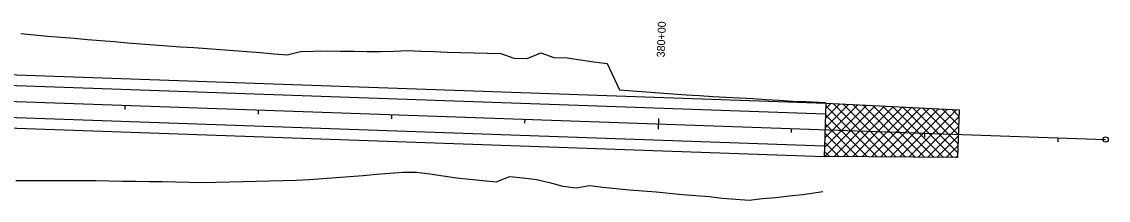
# Model space of a CAD drawing. Extents: x 881426 to 887360, y 1564404 to 1567430.
# Drawn here: x 886545 to 887360, y 1564404 to 1564538 of the extents above; entities that cross this region are included whole.
import ezdxf

# ---------------------------------------------------------------- set-up
doc = ezdxf.new("R2010")
doc.units = 0
for name, color, linetype in [('R_Axis', 7, 'Continuous'), ('R_Horz Alg', 7, 'Continuous'), ('R_Horz Alg Annot', 7, 'Continuous'), ('R_Proposed Const Limits_Cut', 7, 'Continuous'), ('R_Proposed Const Limits_Fill', 7, 'Continuous'), ('R_Proposed Road_Lane', 7, 'Continuous'), ('R_Proposed Road_Shoulder', 7, 'Continuous')]:
    doc.layers.add(name, color=color, linetype=linetype)

msp = doc.modelspace()

# ---------------------------------------------------------------- linework, layer by layer
at = {"layer": 'R_Axis'}
for p, q in [((887146.85, 1564444.07), (887178.58, 1564475.8)), ((887147.1, 1564451.4), (887171.84, 1564476.14)), ((887147.21, 1564437.36), (887185.31, 1564475.46)), ((887147.36, 1564458.72), (887165.11, 1564476.48)), ((887147.61, 1564466.05), (887158.38, 1564476.81)), ((887147.87, 1564473.37), (887151.65, 1564477.15)), ((887147.94, 1564475.39), (887186.33, 1564437)), ((887153.33, 1564477.07), (887193.47, 1564436.93)), ((887154.21, 1564437.29), (887192.04, 1564475.12)), ((887160.78, 1564476.69), (887200.61, 1564436.86)), ((887161.22, 1564437.23), (887198.77, 1564474.78)), ((887168.22, 1564476.32), (887207.75, 1564436.8)), ((887168.23, 1564437.16), (887205.5, 1564474.44)), ((887175.23, 1564437.1), (887212.23, 1564474.1)), ((887175.67, 1564475.94), (887214.88, 1564436.73)), ((887182.24, 1564437.03), (887218.96, 1564473.76)), ((887183.12, 1564475.57), (887222.02, 1564436.67)), ((887189.25, 1564436.97), (887225.7, 1564473.42)), ((887190.56, 1564475.19), (887229.16, 1564436.6)), ((887196.25, 1564436.9), (887232.43, 1564473.08)), ((887198.01, 1564474.82), (887236.29, 1564436.53)), ((887203.26, 1564436.84), (887239.16, 1564472.74)), ((887205.46, 1564474.44), (887243.43, 1564436.47)), ((887210.26, 1564436.77), (887245.89, 1564472.4)), ((887212.9, 1564474.06), (887246.77, 1564440.19)), ((887220.35, 1564473.69), (887247.01, 1564447.03)), ((887227.8, 1564473.31), (887247.25, 1564453.86)), ((887235.25, 1564472.94), (887247.49, 1564460.7)), ((887242.69, 1564472.56), (887247.72, 1564467.53)), ((887147.46, 1564461.72), (887172.06, 1564437.13)), ((887147.7, 1564468.56), (887179.2, 1564437.06)), ((887217.27, 1564436.71), (887247.71, 1564467.15)), ((887147.23, 1564454.89), (887164.92, 1564437.19)), ((887224.28, 1564436.64), (887247.46, 1564459.82)), ((887146.99, 1564448.06), (887157.79, 1564437.26)), ((887231.28, 1564436.58), (887247.2, 1564452.5)), ((887238.29, 1564436.51), (887246.95, 1564445.17)), ((887146.75, 1564441.22), (887150.65, 1564437.33)), ((887245.3, 1564436.45), (887246.69, 1564437.85))]:
    msp.add_line(p, q, dxfattribs=at)
at = {"layer": 'R_Horz Alg'}
msp.add_line((885670.58, 1564508.69), (887357.73, 1564450.04), dxfattribs=at)
at = {"layer": 'R_Horz Alg Annot'}
for points in [[(886622.52, 1564472.59), (886622.63, 1564475.59)], [(886722.46, 1564469.12), (886722.57, 1564472.12)], [(886822.4, 1564465.64), (886822.51, 1564468.64)], [(886922.34, 1564462.17), (886922.45, 1564465.17)], [(887022.53, 1564465.69), (887022.25, 1564457.7)], [(887122.22, 1564455.22), (887122.33, 1564458.22)], [(887222.16, 1564451.75), (887222.27, 1564454.74)], [(887322.1, 1564448.27), (887322.2, 1564451.27)]]:
    msp.add_lwpolyline(points, dxfattribs=at)
msp.add_circle((887357.73, 1564450.04), 2, dxfattribs=at)
at = {"layer": 'R_Proposed Const Limits_Cut'}
for points in [[(886544.46, 1564529.61), (886554.43, 1564528.56), (886564.4, 1564527.67), (886574.38, 1564526.79), (886584.35, 1564525.94), (886594.33, 1564525.12), (886604.31, 1564524.31), (886614.29, 1564523.48), (886624.26, 1564522.66), (886634.24, 1564521.86), (886644.22, 1564521.04), (886654.2, 1564520.31), (886664.18, 1564519.62), (886674.17, 1564519.03), (886684.15, 1564518.31), (886694.13, 1564517.57), (886704.11, 1564516.83), (886714.09, 1564516.09), (886724.07, 1564515.3), (886734.04, 1564514.42), (886744.02, 1564513.56)], [(886540.62, 1564419.35), (886550.63, 1564419.33), (886560.64, 1564419.33), (886570.64, 1564419.33), (886580.65, 1564419.33), (886590.65, 1564419.36), (886600.65, 1564419.18), (886610.65, 1564418.99), (886620.65, 1564418.84), (886630.65, 1564418.68), (886640.66, 1564418.56), (886650.66, 1564418.44), (886660.66, 1564418.18), (886670.65, 1564417.95), (886680.66, 1564417.89), (886690.67, 1564418.01), (886700.68, 1564418.22), (886710.69, 1564418.43), (886720.71, 1564418.68), (886730.72, 1564418.95), (886740.74, 1564419.23), (886750.76, 1564419.55), (886760.78, 1564419.92), (886770.81, 1564420.74), (886780.84, 1564421.42), (886790.87, 1564422.22), (886800.91, 1564423.14), (886810.95, 1564423.93), (886820.98, 1564424.76), (886831.02, 1564425.62), (886841.02, 1564425.51)]]:
    msp.add_lwpolyline(points, dxfattribs=at)
at = {"layer": 'R_Proposed Const Limits_Fill'}
for points in [[(886744.02, 1564513.56), (886754.11, 1564516.05), (886764.13, 1564516.27), (886774.14, 1564516.47), (886784.14, 1564516.29), (886794.14, 1564516.18), (886804.14, 1564516.06), (886814.15, 1564516.1), (886824.16, 1564516.24), (886834.19, 1564516.8), (886844.18, 1564516.29), (886854.17, 1564515.93), (886864.16, 1564515.63), (886874.16, 1564515.31), (886884.15, 1564514.99), (886894.15, 1564514.71), (886904.15, 1564514.44), (886914.03, 1564511), (886924.03, 1564510.77), (886934.18, 1564514.93), (886944.07, 1564511.49), (886954.07, 1564511.33), (886964.02, 1564509.74), (886973.98, 1564508.28), (886983.94, 1564507.04), (886993.26, 1564487.38), (887003.24, 1564486.57), (887013.22, 1564485.9), (887023.2, 1564485.09), (887033.18, 1564484.32), (887043.16, 1564483.62), (887053.14, 1564482.98), (887063.13, 1564482.37), (887073.12, 1564481.8), (887083.1, 1564481.25), (887093.09, 1564480.67), (887103.07, 1564480.03), (887113.06, 1564479.43), (887123.04, 1564478.87), (887133.03, 1564478.44), (887143.03, 1564478.03), (887148.02, 1564477.86)], [(886841.02, 1564425.51), (886850.98, 1564424.17), (886860.93, 1564422.71), (886870.89, 1564421.31), (886880.86, 1564420.18), (886890.83, 1564419.24), (886900.8, 1564418.25), (886910.95, 1564422.4), (886920.92, 1564421.23), (886930.88, 1564419.93), (886940.81, 1564417.66), (886950.72, 1564415.03), (886960.68, 1564413.77), (886970.75, 1564415.58), (886980.71, 1564414.26), (886990.69, 1564413.35), (887000.66, 1564412.33), (887010.64, 1564411.5), (887020.61, 1564410.66), (887030.59, 1564409.76), (887040.56, 1564408.86), (887050.54, 1564407.97), (887060.52, 1564407.28), (887070.49, 1564406.14), (887080.47, 1564405.4), (887090.44, 1564404.44), (887100.49, 1564405.67), (887110.52, 1564406.41), (887120.57, 1564407.83), (887130.61, 1564408.79), (887140.67, 1564410.3), (887145.7, 1564411.04)]]:
    msp.add_lwpolyline(points, dxfattribs=at)
at = {"layer": 'R_Proposed Road_Lane'}
for p, q in [((885670.99, 1564520.68), (887147.73, 1564469.34)), ((885670.16, 1564496.7), (887146.89, 1564445.36))]:
    msp.add_line(p, q, dxfattribs=at)
at = {"layer": 'R_Proposed Road_Shoulder'}
for p, q in [((885671.27, 1564528.68), (887148.01, 1564477.34)), ((885669.88, 1564488.7), (887146.62, 1564437.36)), ((887148.01, 1564477.34), (887146.62, 1564437.36))]:
    msp.add_line(p, q, dxfattribs=at)
msp.add_lwpolyline([(887148.01, 1564477.34), (887247.89, 1564472.3), (887246.64, 1564436.44), (887146.62, 1564437.36)], dxfattribs=at)

# ---------------------------------------------------------------- texts
at = {"layer": 'R_Horz Alg Annot'}
msp.add_text('380+00', height=6, rotation=88.00892, dxfattribs=at).set_placement((887027.12, 1564511.56))

doc.saveas('drawing.dxf')
